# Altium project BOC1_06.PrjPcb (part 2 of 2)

## Sheet BOC_Boot.SchDoc: Board-On-Chip Bootup Circuits
size B; Organization: Altium Limited; Address1: L3, 12a Rodborough Rd; Address2: Frenchs Forest; Address3: NSW; Address4: Australia 2086; Revision: 1.06; SheetNumber: 2; SheetTotal: 16
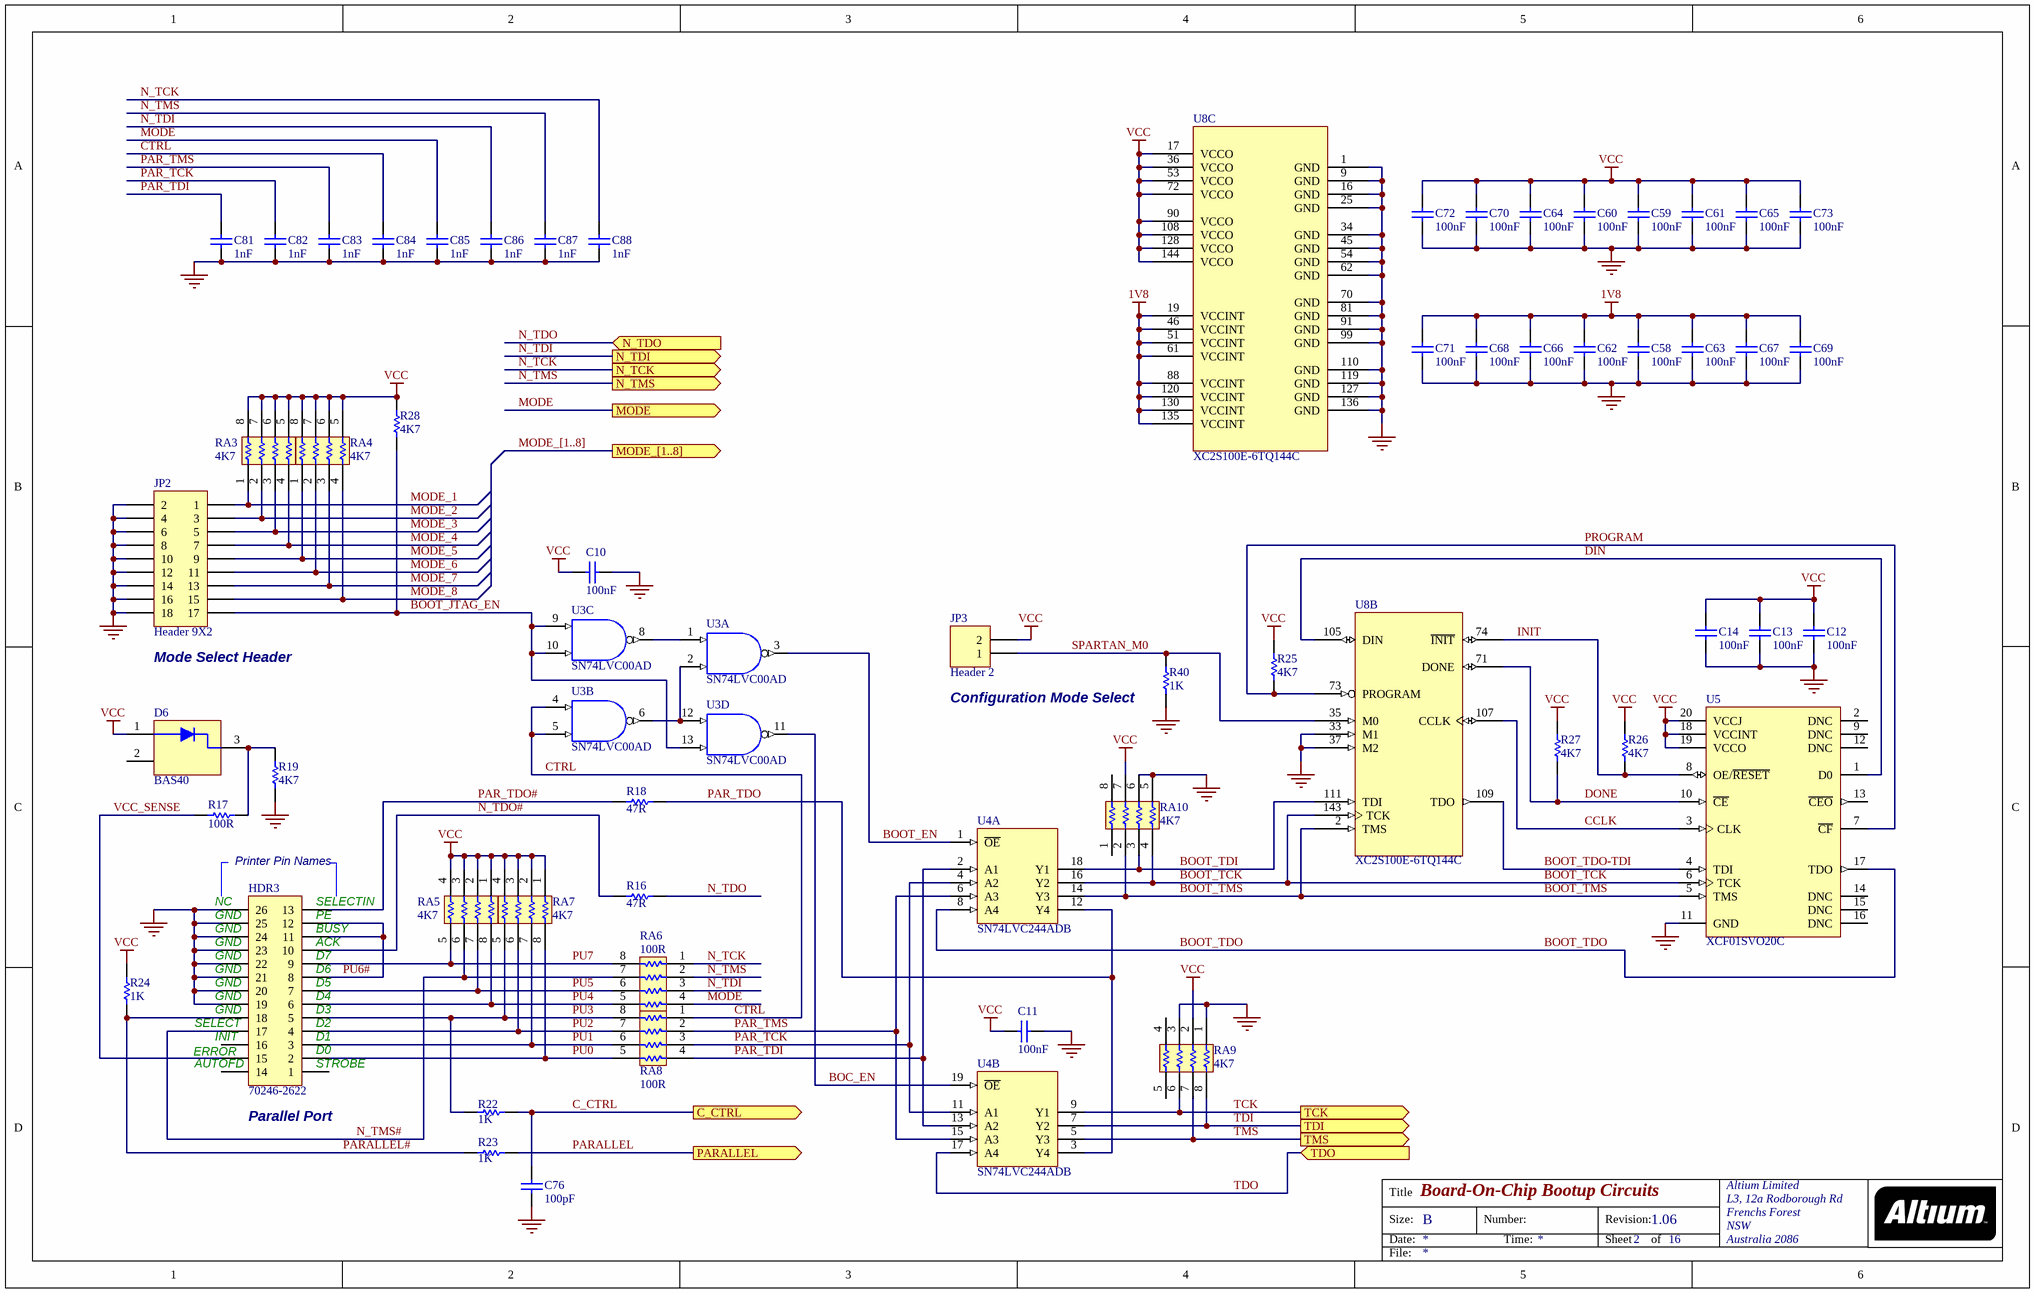
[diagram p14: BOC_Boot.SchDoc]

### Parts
C10  100nF  [CC2012-0805]
C11  100nF  [CC2012-0805]
C12  100nF  [CC2012-0805]
C13  100nF  [CC2012-0805]
C14  100nF  [CC2012-0805]
C58  100nF  [CC2012-0805]
C59  100nF  [CC2012-0805]
C60  100nF  [CC2012-0805]
C61  100nF  [CC2012-0805]
C62  100nF  [CC2012-0805]
C63  100nF  [CC2012-0805]
C64  100nF  [CC2012-0805]
C65  100nF  [CC2012-0805]
C66  100nF  [CC2012-0805]
C67  100nF  [CC2012-0805]
C68  100nF  [CC2012-0805]
C69  100nF  [CC2012-0805]
C70  100nF  [CC2012-0805]
C71  100nF  [CC2012-0805]
C72  100nF  [CC2012-0805]
C73  100nF  [CC2012-0805]
C76  100pF  [CC2012-0805]
C81  1nF  [CC2012-0805]
C82  1nF  [CC2012-0805]
C83  1nF  [CC2012-0805]
C84  1nF  [CC2012-0805]
C85  1nF  [CC2012-0805]
C86  1nF  [CC2012-0805]
C87  1nF  [CC2012-0805]
C88  1nF  [CC2012-0805]
D6  BAS40  [SO-G3]
HDR3  70246-2622  Usage: Parallel Port  [HDR2X13_CEN_LP]
JP2  Header 9X2  Usage: Mode Select Header  [HDR2X9]
JP3  Header 2  Usage: Configuration Mode Select  [HDR1X2]
R16  47R  [CC2012-0805]
R17  100R  [CC2012-0805]
R18  47R  [CC2012-0805]
R19  4K7  [CC2012-0805]
R22  1K  [CC2012-0805]
R23  1K  [CC2012-0805]
R24  1K  [CC2012-0805]
R25  4K7  [CC2012-0805]
R26  4K7  [CC2012-0805]
R27  4K7  [CC2012-0805]
R28  4K7  [CC2012-0805]
R40  1K  [CC2012-0805]
RA3  4K7  [MNR34]
RA4  4K7  [MNR34]
RA5  4K7  [MNR34]
RA6  100R  [MNR34]
RA7  4K7  [MNR34]
RA8  100R  [MNR34]
RA9  4K7  [MNR34]
RA10  4K7  [MNR34]
U3  SN74LVC00AD  [SO-G14/Y2.2]  (parts A,B,C,D of 4)
U4  SN74LVC244ADB  [SSO-G20/P.65]  (parts A,B of 2)
U5  XCF01SVO20C  [VO20]
U8  XC2S100E-6TQ144C  [TQ144]  (parts B,C of 3)

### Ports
C_CTRL (out), MODE (out), MODE_[1..8] (out), N_TCK (out), N_TDI (out), N_TDO (in), N_TMS (out), PARALLEL (out), TCK (out), TDI (out), TDO (in), TMS (out)

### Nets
1V8: C58.1 C62.1 C63.1 C66.1 C67.1 C68.1 C69.1 C71.1 U8.19(VCCINT) U8.46(VCCINT) U8.51(VCCINT) U8.61(VCCINT) U8.88(VCCINT) U8.120(VCCINT) U8.130(VCCINT) U8.135(VCCINT)
GND: C10.2 C11.2 C12.1 C13.1 C14.1 C58.2 C59.2 C60.2 C61.2 C62.2 C63.2 C64.2 C65.2 C66.2 C67.2 C68.2 C69.2 C70.2 C71.2 C72.2 C73.2 C76.2 C81.2 C82.2 C83.2 C84.2 C85.2 C86.2 C87.2 C88.2 HDR3.19 HDR3.20 HDR3.21 HDR3.22 HDR3.23 HDR3.24 HDR3.25 HDR3.26 JP2.2 JP2.4 JP2.6 JP2.8 JP2.10 JP2.12 JP2.14 JP2.16 JP2.18 R19.2 R40.1 RA9.1 RA9.3 RA10.5 RA10.6 U3.7(GND) U4.10(GND) U5.11(GND) U8.1(GND) U8.9(GND) U8.16(GND) U8.25(GND) U8.33(M1) U8.34(GND) U8.37(M2) U8.45(GND) U8.54(GND) U8.62(GND) U8.70(GND) U8.81(GND) U8.91(GND) U8.99(GND) U8.110(GND) U8.119(GND) U8.127(GND) U8.136(GND)
VCC: C10.1 C11.1 C12.2 C13.2 C14.2 C59.1 C60.1 C61.1 C64.1 C65.1 C70.1 C72.1 C73.1 D6.1 JP3.2 R24.2 R25.1 R26.1 R27.1 R28.2 RA3.5 RA3.6 RA3.7 RA3.8 RA4.5 RA4.6 RA4.7 RA4.8 RA5.1 RA5.2 RA5.3 RA5.4 RA7.1 RA7.2 RA7.3 RA7.4 RA9.2 RA10.7 U3.14(VDD) U4.20(VCC) U5.18(VCCINT) U5.19(VCCO) U5.20(VCCJ) U8.17(VCCO) U8.36(VCCO) U8.53(VCCO) U8.72(VCCO) U8.90(VCCO) U8.108(VCCO) U8.128(VCCO) U8.144(VCCO)
BOC_EN: U3.11(Y) U4.19(~{OE})
BOOT_EN: U3.3(Y) U4.1(~{OE})
BOOT_JTAG_EN: JP2.17 R28.1 U3.9(A) U3.10(B) U3.13(B)
BOOT_TCK: RA10.4 U4.16(Y2) U5.6(TCK) U8.143(TCK)
BOOT_TDI: RA10.3 U4.18(Y1) U8.111(TDI)
BOOT_TDO: U4.8(A4) U5.17(TDO)
BOOT_TDO-TDI: U5.4(TDI) U8.109(TDO)
BOOT_TMS: RA10.2 U4.14(Y3) U5.5(TMS) U8.2(TMS)
C_CTRL: C76.1 R22.2 ; port C_CTRL
CCLK: U5.3(CLK) U8.107(CCLK)
CTRL: C84.1 RA8.1 U3.4(A) U3.5(B)
DIN: U5.1(D0) U8.105(DIN)
DONE: R27.2 U5.10(~{CE}) U8.71(DONE)
INIT: R26.2 U5.8(OE/~{RESET}) U8.74(~{INIT})
MODE: C85.1 RA6.4 ; port MODE
MODE_1: JP2.1 RA3.1
MODE_2: JP2.3 RA3.2
MODE_3: JP2.5 RA3.3
MODE_4: JP2.7 RA3.4
MODE_5: JP2.9 RA4.1
MODE_6: JP2.11 RA4.2
MODE_7: JP2.13 RA4.3
MODE_8: JP2.15 RA4.4
N_TCK: C88.1 RA6.1 ; port N_TCK
N_TDI: C86.1 RA6.3 ; port N_TDI
N_TDO: R16.2 ; port N_TDO
N_TDO#: HDR3.10 R16.1
N_TMS: C87.1 RA6.2 ; port N_TMS
N_TMS#: HDR3.17 RA5.6 RA6.7
PAR_TCK: C82.1 RA8.3 U4.4(A2) U4.11(A1)
PAR_TDI: C81.1 RA8.4 U4.2(A1) U4.13(A2)
PAR_TDO: R18.2 U4.3(Y4) U4.12(Y4)
PAR_TDO#: HDR3.13 R18.1
PAR_TMS: C83.1 RA8.2 U4.6(A3) U4.15(A3)
PARALLEL: R23.2 ; port PARALLEL
PARALLEL#: HDR3.18 R23.1 R24.1
PROGRAM: R25.2 U5.7(~{CF}) U8.73(PROGRAM)
PU0: HDR3.2 RA7.8 RA8.5
PU1: HDR3.3 RA7.7 RA8.6
PU2: HDR3.4 RA7.6 RA8.7
PU3: HDR3.5 R22.1 RA7.5 RA8.8
PU4: HDR3.6 RA5.8 RA6.5
PU5: HDR3.7 RA5.7 RA6.6
PU6#: HDR3.8 HDR3.11 HDR3.12
PU7: HDR3.9 RA5.5 RA6.8
SPARTAN_M0: JP3.1 R40.2 U8.35(M0)
TCK: RA9.6 U4.9(Y1) ; port TCK
TDI: RA9.8 U4.7(Y2) ; port TDI
TDO: U4.17(A4) ; port TDO
TMS: RA9.7 U4.5(Y3) ; port TMS
VCC_SENSE: HDR3.15 R17.1
NetD6_3: D6.3 R17.2 R19.1
NetU3_1: U3.1(A) U3.8(Y)
NetU3_2: U3.2(B) U3.6(Y) U3.12(A)

Not connected (* = marked no-connect by the designer): D6 2; HDR3 1 14 16; RA9 4 5; RA10 1 8; U5 2(DNC) 9(DNC) 12(DNC) 13(~{CEO}) 14(DNC) 15(DNC) 16(DNC)

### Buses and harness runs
bus MODE_[1..8] = port MODE_[1..8]

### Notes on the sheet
- (near HDR3) NC
- Printer Pin Names
- (near HDR3) SELECTIN
- (near HDR3) GND
- (near HDR3) PE
- (near HDR3) BUSY
- (near HDR3) ACK
- (near HDR3) D6
- (near HDR3) D7
- (near HDR3) SELECT
- (near HDR3) INIT
- (near HDR3) D1
- (near HDR3) D2
- (near HDR3) D3
- (near HDR3) D4
- (near HDR3) D5
- (near HDR3) ERROR
- (near HDR3) AUTOFD
- (near HDR3) STROBE
- (near HDR3) D0

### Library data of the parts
C10-C14 C58-C73 C76 C81-C88 = CAP: Capacitor; Fitted: True
D6 = BAS40: Shottky Diode; Fitted: True
HDR3 = Header 13X2A: Header, 13-Pin, Dual row; Manufacturer: Generic Components; Class I: Connector; Fitted: True
JP2 = Header 9X2: Header, 9-Pin, Dual row; Manufacturer: Generic Components; Class I: Connector; Fitted: True
JP3 = Header 2: Header, 2-Pin; Manufacturer: Generic Components; Class I: Connector; Fitted: True
R16-R19 R22-R28 R40 = RES: Resistor; Fitted: True
RA3-RA10 = MNR34: 3216x4 Resistor Array; Fitted: True
U3 = MC74HC00AD: Quad 2-Input NAND Gate; Manufacturer: Motorola; Package Information: Latest Revision: 1991; Class I: Logic; Fitted: True
U4 = 74LVC244A: Octal Buffer/Driver with 3-State Outputs; Manufacturer: Philips; Package Information: Latest Revision: 1998; Class I: Logic; Class II: Buffer/Line Driver; Fitted: True
U5 = XCF01SVO20C: XCF00S Series, Platform Flash In-System Programmable Configuration 3.3V PROM, 1-Megabit, Commercial Grade; Manufacturer: Xilinx; Package Information: Latest Revision: ver1.0, May-2003; Class I: Memory; Code - JEDEC: MO-153-AC; Fitted: True
U8 = XC2S100E-6TQ144C: Spartan-IIE 1.8V FPGA, 144-Pin TQFP, Standard Performance, Commercial Grade; Manufacturer: Xilinx; Package Information: Latest Revision: ver1.1, Oct-2002; Class I: Field Programmable Gate Array; Code - JEDEC: MS-026-BFB; Code - IPC: SQFP20X20-144; Fitted: True

## Sheet BOC_Audio.SchDoc: Board-On-Chip Audio Interface
size A; Organization: Altium Limited; Address1: L3, 12a Rodborough Rd; Address2: Frenchs Forest; Address3: NSW; Address4: Australia 2086; Revision: 1.06; SheetNumber: 3; SheetTotal: 16
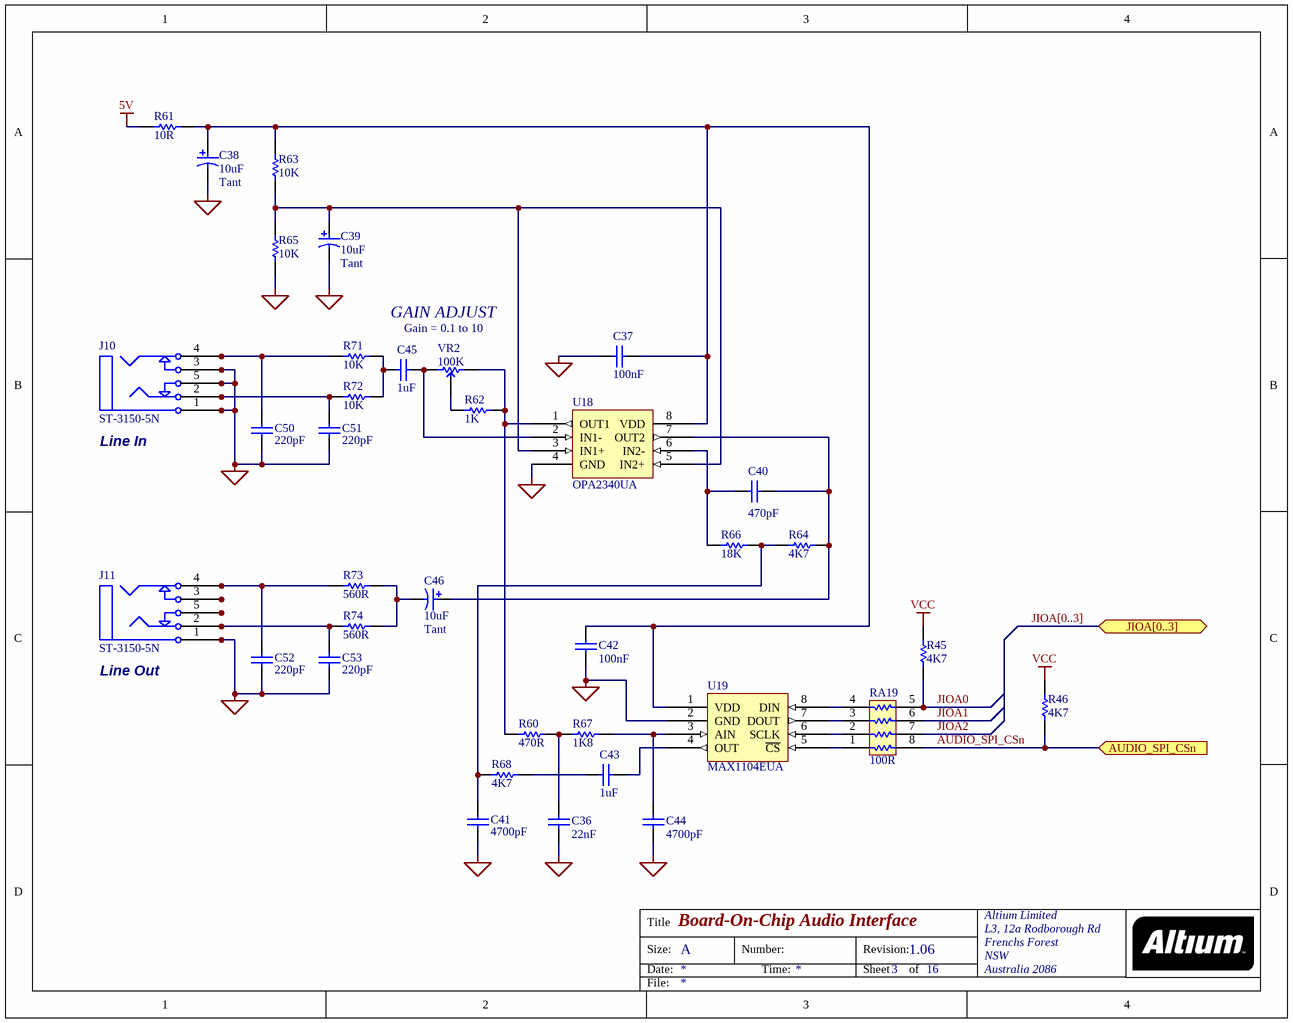
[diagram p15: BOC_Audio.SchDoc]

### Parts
C36  22nF  [CC2012-0805]
C37  100nF  [CC2012-0805]
C38  10uF  Capacitor Type: Tant  [MCCT-B]
C39  10uF  Capacitor Type: Tant  [MCCT-B]
C40  470pF  [CC2012-0805]
C41  4700pF  [CC2012-0805]
C42  100nF  [CC2012-0805]
C43  1uF  [C3216-1206]
C44  4700pF  [CC2012-0805]
C45  1uF  [C3216-1206]
C46  10uF  Capacitor Type: Tant  [MCCT-B]
C50  220pF  [CC2012-0805]
C51  220pF  [CC2012-0805]
C52  220pF  [CC2012-0805]
C53  220pF  [CC2012-0805]
J10  ST-3150-5N  [ST-3150-5N]
J11  ST-3150-5N  [ST-3150-5N]
R45  4K7  [CC2012-0805]
R46  4K7  [CC2012-0805]
R60  470R  [CC2012-0805]
R61  10R  [CC2012-0805]
R62  1K  [CC2012-0805]
R63  10K  [CC2012-0805]
R64  4K7  [CC2012-0805]
R65  10K  [CC2012-0805]
R66  18K  [CC2012-0805]
R67  1K8  [CC2012-0805]
R68  4K7  [CC2012-0805]
R71  10K  [CC2012-0805]
R72  10K  [CC2012-0805]
R73  560R  [CC2012-0805]
R74  560R  [CC2012-0805]
RA19  100R  [MNR34]
U18  OPA2340UA  [SO-G8]
U19  MAX1104EUA  [TSSO3X5-G8/X.35]
VR2  100K  [POT4MM-2]

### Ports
AUDIO_SPI_CSn (in), JIOA[0..3] (bidir)

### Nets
5V: R61.1
AGND: C36.2 C37.1 C38.2 C39.2 C41.2 C42.2 C44.2 C50.2 C51.2 C52.2 C53.2 J10.1 J10.1A J10.1B J10.3 J10.3A J10.3B J10.5 J10.5A J10.5B J11.1 J11.1A J11.1B R65.1 U18.4(GND) U19.2(GND)
VCC: R45.2 R46.2
AUDIO_SPI_CSn: R46.1 RA19.8 ; port AUDIO_SPI_CSn
JIOA0: R45.1 RA19.5
JIOA1: RA19.6
JIOA2: RA19.7
NetC36_1: C36.1 R60.2 R67.1
NetC37_2: C37.2 C38.1 C42.1 R61.2 R63.2 U18.8(VDD) U19.1(VDD)
NetC39_1: C39.1 R63.1 R65.2 U18.3(IN1+) U18.5(IN2+)
NetC40_1: C40.1 R66.2 U18.6(IN2-)
NetC40_2: C40.2 C46.1 R64.1 U18.7(OUT2)
NetC41_1: C41.1 R64.2 R66.1 R68.1
NetC43_1: C43.1 R68.2
NetC43_2: C43.2 U19.4(OUT)
NetC44_1: C44.1 R67.2 U19.3(AIN)
NetC45_1: C45.1 R71.2 R72.2
NetC45_2: C45.2 U18.2(IN1-) VR2.CCW(-)
NetC46_2: C46.2 R73.2 R74.2
NetC50_1: C50.1 J10.4 J10.4A J10.4B R71.1
NetC51_1: C51.1 J10.2 J10.2A J10.2B R72.1
NetC52_1: C52.1 J11.4 J11.4A J11.4B R73.1
NetC53_1: C53.1 J11.2 J11.2A J11.2B R74.1
NetJ11_3: J11.3 J11.3A J11.3B
NetJ11_5: J11.5 J11.5A J11.5B
NetR60_1: R60.1 R62.2 U18.1(OUT1) VR2.CW(+)
NetR62_1: R62.1 VR2.W
NetRA19_1: RA19.1 U19.5(~{CS})
NetRA19_2: RA19.2 U19.6(SCLK)
NetRA19_3: RA19.3 U19.7(DOUT)
NetRA19_4: RA19.4 U19.8(DIN)

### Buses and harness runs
bus JIOA[0..3] = port JIOA[0..3]

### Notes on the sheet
- GAIN ADJUST
- Gain = 0.1 to 10
- (near J10) Line In
- (near J11) Line Out

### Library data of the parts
C36 C37 C40-C45 C50-C53 = CAP: Capacitor; Fitted: True
C38 C39 C46 = CAP_POLAR: Polar Capacitor; Fitted: True
J10 J11 = ST-3150-5N: 3-Conductor Jack with 2 break contacts (normals) and 2 auxiliary make contacts; Manufacturer: Kycon; Class I: Connector; Fitted: True
R45 R46 R60-R68 R71-R74 = RES: Resistor; Fitted: True
RA19 = MNR34: 3216x4 Resistor Array; Fitted: True
U18 = OPA2340UA: Manufacturer: Burr-Brown; Fitted: True
U19 = MAX1104EUA: 8 bit CODEC with 4 wire logic interface; Manufacturer: Maxim; Fitted: True
VR2 = POT_M: Potentiometer; Fitted: True

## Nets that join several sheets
1V8: BOC_PWR (C21.1 C23.1 R42.1 U9.2), BOC_Boot (16 pins)
5V: BOC_IO (JP5.2 JP6.2), BOC_PWR (9 pins), BOC_ADC_DAC (HDR8.2), BOC_CAN (C4.1 J2.4 U2.3), BOC_LCD (LCD1.15 Q2.2 R30.1 R38.1), BOC_Spartan (R5.1), BOC_DAUGHTER (J8.97 J8.99 J9.97 J9.99), BOC_Audio (R61.1)
AGND: BOC_ADC_DAC (12 pins), BOC_Audio (26 pins)
GND: BOC_SRAM (6 pins), BOC_IO (HDR9.20 HDR10.20), BOC_KB (SW17.3 SW17.4), BOC_PWR (42 pins), BOC_RS232 (7 pins), BOC_ADC_DAC (HDR8.14 R80.1), BOC_CAN (7 pins), BOC_LED_DIPSWITCH (16 pins), BOC_CLK_ADJ (8 pins), BOC_LCD (16 pins), BOC_VGA_KB_MOUSE (17 pins), BOC_Spartan (36 pins), BOC_DAUGHTER (22 pins), BOC_Boot (74 pins)
VCC: BOC_SRAM (7 pins), BOC_IO (JP5.3 JP6.3), BOC_KB (5 pins), BOC_PWR (C16.1 C25.1 R47.1 U10.2), BOC_RS232 (C1.1 C2.1 C3.1 U1.16), BOC_ADC_DAC (R75.2 R77.1 R79.1), BOC_LED_DIPSWITCH (8 pins), BOC_CLK_ADJ (7 pins), BOC_LCD (5 pins), BOC_VGA_KB_MOUSE (12 pins), BOC_Spartan (32 pins), BOC_DAUGHTER (J8.94 J8.96 J9.94 J9.96), BOC_Boot (51 pins), BOC_Audio (R45.2 R46.2)
VCCINT: BOC_PWR (C24.1 C35.1 R56.1 U11.2), BOC_DAUGHTER (J8.93 J8.95 J9.93 J9.95)
AUDIO_SPI_CSn: BOC_DAUGHTER (J8.11), BOC_Audio (R46.1 RA19.8)
BLUE0: BOC_VGA_KB_MOUSE (R14.1), BOC_DAUGHTER (J8.14)
BLUE1: BOC_VGA_KB_MOUSE (R15.1), BOC_DAUGHTER (J8.16)
BOC_CTS: BOC_RS232 (R9.1), BOC_DAUGHTER (J8.13)
BOC_RTS: BOC_RS232 (U1.10), BOC_DAUGHTER (J8.17)
BOC_RX: BOC_RS232 (R1.1), BOC_DAUGHTER (J8.19)
BOC_TX: BOC_RS232 (U1.11), BOC_DAUGHTER (J8.15)
BUZZER: BOC_LCD (R37.1), BOC_DAUGHTER (J9.24)
C_CTRL: BOC_Spartan (U8.80), BOC_Boot (C76.1 R22.2)
C_SPI_CLOCK_CLK: BOC_CLK_ADJ (U12.8), BOC_Spartan (U8.141)
C_SPI_CLOCK_SEL: BOC_CLK_ADJ (R50.1 U12.9), BOC_Spartan (U8.142)
C_SPI_DIN: BOC_CLK_ADJ (U12.12), BOC_Spartan (U6.5 U7.5 U8.140)
CAN_RXD: BOC_CAN (R4.1), BOC_DAUGHTER (J8.4)
CAN_TXD: BOC_CAN (U2.1), BOC_DAUGHTER (J8.2)
FPGA_AUX0: BOC_Spartan (U8.41), BOC_DAUGHTER (J8.86)
FPGA_AUX1: BOC_Spartan (U8.42), BOC_DAUGHTER (J8.88)
FPGA_AUX2: BOC_Spartan (U8.43), BOC_DAUGHTER (J8.90)
FPGA_AUX3: BOC_Spartan (U8.44), BOC_DAUGHTER (J8.92)
FPGA_CCLK: BOC_Spartan (U8.24), BOC_DAUGHTER (J8.66)
FPGA_CLK: BOC_CLK_ADJ (R51.2 R53.2), BOC_Spartan (U8.126), BOC_DAUGHTER (J9.2)
FPGA_CLK_1: BOC_Spartan (U8.3), BOC_DAUGHTER (J8.30)
FPGA_CLK_2: BOC_Spartan (U8.4), BOC_DAUGHTER (J8.32)
FPGA_DIN: BOC_Spartan (U8.23), BOC_DAUGHTER (J8.64)
FPGA_DONE: BOC_Spartan (U8.29), BOC_DAUGHTER (J8.74)
FPGA_ID0: BOC_Spartan (U8.10), BOC_DAUGHTER (J8.42)
FPGA_ID1: BOC_Spartan (U8.8), BOC_DAUGHTER (J8.40)
FPGA_ID2: BOC_Spartan (U8.7), BOC_DAUGHTER (J8.38)
FPGA_ID3: BOC_Spartan (U8.6), BOC_DAUGHTER (J8.36)
FPGA_INIT: BOC_Spartan (U8.26), BOC_DAUGHTER (J8.68)
FPGA_INSTALLED: BOC_Spartan (R44.2 U8.5), BOC_DAUGHTER (J8.34)
FPGA_M0: BOC_Spartan (U8.21), BOC_DAUGHTER (J8.60)
FPGA_M1: BOC_Spartan (U8.20), BOC_DAUGHTER (J8.58)
FPGA_M2: BOC_Spartan (U8.18), BOC_DAUGHTER (J8.56)
FPGA_PROGRAM: BOC_Spartan (U8.22), BOC_DAUGHTER (J8.62)
FPGA_TCK: BOC_Spartan (U8.28), BOC_DAUGHTER (J8.72)
FPGA_TDI: BOC_Spartan (U8.31), BOC_DAUGHTER (J8.78)
FPGA_TDO: BOC_Spartan (RA16.1), BOC_DAUGHTER (J8.54)
FPGA_TMS: BOC_Spartan (U8.27), BOC_DAUGHTER (J8.70)
GREEN0: BOC_VGA_KB_MOUSE (R12.1), BOC_DAUGHTER (J8.10)
GREEN1: BOC_VGA_KB_MOUSE (R13.1), BOC_DAUGHTER (J8.12)
HDRIVE: BOC_VGA_KB_MOUSE (D4.3 J3.13), BOC_DAUGHTER (J8.18)
IO0: BOC_IO (HDR9.2), BOC_DAUGHTER (J9.7)
IO1: BOC_IO (HDR9.3), BOC_DAUGHTER (J9.9)
IO2: BOC_IO (HDR9.4), BOC_DAUGHTER (J9.11)
IO3: BOC_IO (HDR9.5), BOC_DAUGHTER (J9.13)
IO4: BOC_IO (HDR9.6), BOC_DAUGHTER (J9.15)
IO5: BOC_IO (HDR9.7), BOC_DAUGHTER (J9.17)
IO6: BOC_IO (HDR9.8), BOC_DAUGHTER (J9.19)
IO7: BOC_IO (HDR9.9), BOC_DAUGHTER (J9.21)
IO8: BOC_IO (HDR9.10), BOC_DAUGHTER (J9.23)
IO9: BOC_IO (HDR9.11), BOC_DAUGHTER (J9.25)
IO10: BOC_IO (HDR9.12), BOC_DAUGHTER (J9.27)
IO11: BOC_IO (HDR9.13), BOC_DAUGHTER (J9.29)
IO12: BOC_IO (HDR9.14), BOC_DAUGHTER (J9.31)
IO13: BOC_IO (HDR9.15), BOC_DAUGHTER (J9.33)
IO14: BOC_IO (HDR9.16), BOC_DAUGHTER (J9.35)
IO15: BOC_IO (HDR9.17), BOC_DAUGHTER (J9.37)
IO16: BOC_IO (HDR9.18), BOC_DAUGHTER (J9.39)
IO17: BOC_IO (HDR9.19), BOC_DAUGHTER (J9.41)
IO18: BOC_IO (HDR10.2), BOC_DAUGHTER (J9.43)
IO19: BOC_IO (HDR10.3), BOC_DAUGHTER (J9.45)
IO20: BOC_IO (HDR10.4), BOC_DAUGHTER (J9.47)
IO21: BOC_IO (HDR10.5), BOC_DAUGHTER (J9.49)
IO22: BOC_IO (HDR10.6), BOC_DAUGHTER (J9.51)
IO23: BOC_IO (HDR10.7), BOC_DAUGHTER (J9.53)
IO24: BOC_IO (HDR10.8), BOC_DAUGHTER (J9.55)
IO25: BOC_IO (HDR10.9), BOC_DAUGHTER (J9.57)
IO26: BOC_IO (HDR10.10), BOC_DAUGHTER (J9.59)
IO27: BOC_IO (HDR10.11), BOC_DAUGHTER (J9.61)
IO28: BOC_IO (HDR10.12), BOC_DAUGHTER (J9.63)
IO29: BOC_IO (HDR10.13), BOC_DAUGHTER (J9.65)
IO30: BOC_IO (HDR10.14), BOC_DAUGHTER (J9.67)
IO31: BOC_IO (HDR10.15), BOC_DAUGHTER (J9.69)
IO32: BOC_IO (HDR10.16), BOC_DAUGHTER (J9.71)
IO33: BOC_IO (HDR10.17), BOC_DAUGHTER (J9.73)
IO34: BOC_IO (HDR10.18), BOC_DAUGHTER (J9.75)
IO35: BOC_IO (HDR10.19), BOC_DAUGHTER (J9.77)
JIOA0: BOC_Spartan (RA20.4), BOC_DAUGHTER (J8.3), BOC_Audio (R45.1 RA19.5)
JIOA1: BOC_Spartan (RA20.3), BOC_DAUGHTER (J8.5), BOC_Audio (RA19.6)
JIOA2: BOC_Spartan (RA20.2), BOC_DAUGHTER (J8.7), BOC_Audio (RA19.7)
JIOA3: BOC_Spartan (RA20.1), BOC_DAUGHTER (J8.9)
JIOB0: BOC_Spartan (RA17.1), BOC_DAUGHTER (J8.83)
JIOB1: BOC_Spartan (RA17.2), BOC_DAUGHTER (J8.85)
JIOB2: BOC_Spartan (RA17.3), BOC_DAUGHTER (J8.87)
JIOB3: BOC_Spartan (RA17.4), BOC_DAUGHTER (J8.89)
KBCLOCK: BOC_VGA_KB_MOUSE (J4.5 RA2.1), BOC_DAUGHTER (J8.22)
KBDATA: BOC_VGA_KB_MOUSE (J4.1 RA2.2), BOC_DAUGHTER (J8.24)
LCD_BCKL: BOC_LCD (R35.1), BOC_DAUGHTER (J9.22)
LCD_E: BOC_LCD (LCD1.6 R29.1 U16.2), BOC_DAUGHTER (J9.26)
LED0: BOC_LED_DIPSWITCH (LED0.1), BOC_DAUGHTER (J9.60)
LED1: BOC_LED_DIPSWITCH (LED1.1), BOC_DAUGHTER (J9.62)
LED2: BOC_LED_DIPSWITCH (LED2.1), BOC_DAUGHTER (J9.64)
LED3: BOC_LED_DIPSWITCH (LED3.1), BOC_DAUGHTER (J9.66)
LED4: BOC_LED_DIPSWITCH (LED4.1), BOC_DAUGHTER (J9.68)
LED5: BOC_LED_DIPSWITCH (LED5.1), BOC_DAUGHTER (J9.70)
LED6: BOC_LED_DIPSWITCH (LED6.1), BOC_DAUGHTER (J9.72)
LED7: BOC_LED_DIPSWITCH (LED7.1), BOC_DAUGHTER (J9.74)
MODE: BOC_Spartan (U8.82), BOC_Boot (C85.1 RA6.4)
MODE_1: BOC_Spartan (U8.97), BOC_Boot (JP2.1 RA3.1)
MODE_2: BOC_Spartan (U8.96), BOC_Boot (JP2.3 RA3.2)
MODE_3: BOC_Spartan (U8.95), BOC_Boot (JP2.5 RA3.3)
MODE_4: BOC_Spartan (U8.94), BOC_Boot (JP2.7 RA3.4)
MODE_5: BOC_Spartan (U8.93), BOC_Boot (JP2.9 RA4.1)
MODE_6: BOC_Spartan (U8.92), BOC_Boot (JP2.11 RA4.2)
MODE_7: BOC_Spartan (U8.89), BOC_Boot (JP2.13 RA4.3)
MODE_8: BOC_Spartan (U8.87), BOC_Boot (JP2.15 RA4.4)
MOUSECLOCK: BOC_VGA_KB_MOUSE (J5.5 RA2.3), BOC_DAUGHTER (J8.26)
MOUSEDATA: BOC_VGA_KB_MOUSE (J5.1 RA2.4), BOC_DAUGHTER (J8.28)
N_TCK: BOC_Spartan (U8.85), BOC_Boot (C88.1 RA6.1)
N_TDI: BOC_Spartan (U8.83), BOC_Boot (C86.1 RA6.3)
N_TDO: BOC_Spartan (U8.86), BOC_Boot (R16.2)
N_TMS: BOC_Spartan (U8.84), BOC_Boot (C87.1 RA6.2)
NEXUS_TCK: BOC_Spartan (RA16.3), BOC_DAUGHTER (J8.82)
NEXUS_TDI: BOC_Spartan (RA16.4), BOC_DAUGHTER (J8.84)
NEXUS_TDO: BOC_Spartan (U8.30), BOC_DAUGHTER (J8.76)
NEXUS_TMS: BOC_Spartan (RA16.2), BOC_DAUGHTER (J8.80)
PARALLEL: BOC_Spartan (U8.79), BOC_Boot (R23.2)
RAM0_DATA0: BOC_SRAM (U15.11), BOC_LCD (U17.11), BOC_DAUGHTER (J9.42)
RAM0_DATA1: BOC_SRAM (U15.10), BOC_LCD (U17.12), BOC_DAUGHTER (J9.40)
RAM0_DATA2: BOC_SRAM (U15.22), BOC_LCD (U17.13), BOC_DAUGHTER (J9.38)
RAM0_DATA3: BOC_SRAM (U15.23), BOC_LCD (U17.14), BOC_DAUGHTER (J9.36)
RAM0_DATA4: BOC_SRAM (U15.7), BOC_LCD (U17.15), BOC_DAUGHTER (J9.34)
RAM0_DATA5: BOC_SRAM (U15.26), BOC_LCD (U17.16), BOC_DAUGHTER (J9.32)
RAM0_DATA6: BOC_SRAM (U15.6), BOC_LCD (U17.17), BOC_DAUGHTER (J9.30)
RAM0_DATA7: BOC_SRAM (U15.27), BOC_LCD (U17.18), BOC_DAUGHTER (J9.28)
RAM0_OE: BOC_SRAM (U15.28), BOC_DAUGHTER (J8.41)
RAM0_WE: BOC_SRAM (U15.12), BOC_DAUGHTER (J8.79)
RAM1_DATA0: BOC_SRAM (U14.6), BOC_DAUGHTER (J8.45)
RAM1_DATA1: BOC_SRAM (U14.7), BOC_DAUGHTER (J8.49)
RAM1_DATA2: BOC_SRAM (U14.10), BOC_DAUGHTER (J8.53)
RAM1_DATA3: BOC_SRAM (U14.11), BOC_DAUGHTER (J8.57)
RAM1_DATA4: BOC_SRAM (U14.22), BOC_DAUGHTER (J8.55)
RAM1_DATA5: BOC_SRAM (U14.23), BOC_DAUGHTER (J8.51)
RAM1_DATA6: BOC_SRAM (U14.26), BOC_DAUGHTER (J8.47)
RAM1_DATA7: BOC_SRAM (U14.27), BOC_DAUGHTER (J8.43)
RAM1_OE: BOC_SRAM (U14.28), BOC_DAUGHTER (J8.39)
RAM1_WE: BOC_SRAM (U14.12), BOC_DAUGHTER (J8.61)
RAM_ADDR0: BOC_SRAM (U14.1 U15.1), BOC_LCD (LCD1.4), BOC_DAUGHTER (J8.21)
RAM_ADDR1: BOC_SRAM (U14.2 U15.2), BOC_LCD (LCD1.5 U17.1), BOC_DAUGHTER (J8.25)
RAM_ADDR2: BOC_SRAM (U14.3 U15.3), BOC_DAUGHTER (J8.29)
RAM_ADDR3: BOC_SRAM (U14.4 U15.4), BOC_DAUGHTER (J8.33)
RAM_ADDR4: BOC_SRAM (U14.13 U15.13), BOC_DAUGHTER (J8.65)
RAM_ADDR5: BOC_SRAM (U14.14 U15.14), BOC_DAUGHTER (J8.69)
RAM_ADDR6: BOC_SRAM (U14.15 U15.15), BOC_DAUGHTER (J8.73)
RAM_ADDR7: BOC_SRAM (U14.16 U15.16), BOC_DAUGHTER (J8.77)
RAM_ADDR8: BOC_SRAM (U14.17 U15.17), BOC_DAUGHTER (J8.75)
RAM_ADDR9: BOC_SRAM (U14.18 U15.18), BOC_DAUGHTER (J8.71)
RAM_ADDR10: BOC_SRAM (U14.19 U15.19), BOC_DAUGHTER (J8.67)
RAM_ADDR11: BOC_SRAM (U14.20 U15.20), BOC_DAUGHTER (J8.63)
RAM_ADDR12: BOC_SRAM (U14.21 U15.21), BOC_DAUGHTER (J8.59)
RAM_ADDR13: BOC_SRAM (U14.29 U15.29), BOC_DAUGHTER (J8.35)
RAM_ADDR14: BOC_SRAM (U14.30 U15.30), BOC_DAUGHTER (J8.31)
RAM_ADDR15: BOC_SRAM (U14.31 U15.31), BOC_DAUGHTER (J8.27)
RAM_ADDR16: BOC_SRAM (U14.32 U15.32), BOC_DAUGHTER (J8.23)
RAM_CS: BOC_SRAM (R59.2 U14.5 U15.5), BOC_DAUGHTER (J8.37)
RED0: BOC_VGA_KB_MOUSE (R10.1), BOC_DAUGHTER (J8.6)
RED1: BOC_VGA_KB_MOUSE (R11.1), BOC_DAUGHTER (J8.8)
REF_CLK: BOC_CLK_ADJ (R52.2 R54.2), BOC_Spartan (U8.129), BOC_DAUGHTER (J9.4)
SCL: BOC_ADC_DAC (HDR8.3 R78.1 R79.2), BOC_DAUGHTER (J9.5)
SDA: BOC_ADC_DAC (HDR8.4 R76.1 R77.2), BOC_DAUGHTER (J9.3)
SPI_CLK: BOC_Spartan (U8.12), BOC_DAUGHTER (J8.46)
SPI_DIN: BOC_Spartan (U8.11), BOC_DAUGHTER (J8.44)
SPI_DOUT: BOC_Spartan (U8.14), BOC_DAUGHTER (J8.50)
SPI_MODE: BOC_Spartan (U8.15), BOC_DAUGHTER (J8.52)
SPI_SEL: BOC_Spartan (U8.13), BOC_DAUGHTER (J8.48)
SW0: BOC_LED_DIPSWITCH (RA21.1 S2.1), BOC_DAUGHTER (J9.44)
SW1: BOC_LED_DIPSWITCH (RA21.2 S2.2), BOC_DAUGHTER (J9.46)
SW2: BOC_LED_DIPSWITCH (RA21.3 S2.3), BOC_DAUGHTER (J9.48)
SW3: BOC_LED_DIPSWITCH (RA21.4 S2.4), BOC_DAUGHTER (J9.50)
SW4: BOC_LED_DIPSWITCH (RA22.1 S2.5), BOC_DAUGHTER (J9.52)
SW5: BOC_LED_DIPSWITCH (RA22.2 S2.6), BOC_DAUGHTER (J9.54)
SW6: BOC_LED_DIPSWITCH (RA22.3 S2.7), BOC_DAUGHTER (J9.56)
SW7: BOC_LED_DIPSWITCH (RA22.4 S2.8), BOC_DAUGHTER (J9.58)
SWC0: BOC_KB (9 pins), BOC_DAUGHTER (J9.18)
SWC1: BOC_KB (9 pins), BOC_DAUGHTER (J9.16)
SWC2: BOC_KB (9 pins), BOC_DAUGHTER (J9.14)
SWC3: BOC_KB (9 pins), BOC_DAUGHTER (J9.6)
SWR0: BOC_KB (8 pins), BOC_DAUGHTER (J9.20)
SWR1: BOC_KB (8 pins), BOC_DAUGHTER (J9.12)
SWR2: BOC_KB (8 pins), BOC_DAUGHTER (J9.10)
SWR3: BOC_KB (8 pins), BOC_DAUGHTER (J9.8)
TCK: BOC_Spartan (U8.78), BOC_Boot (RA9.6 U4.9)
TDI: BOC_Spartan (U8.77), BOC_Boot (RA9.8 U4.7)
TDO: BOC_Spartan (U8.75), BOC_Boot (U4.17)
TEST: BOC_KB (R55.2 SW17.1 SW17.2), BOC_DAUGHTER (J8.81)
TMS: BOC_Spartan (U8.76), BOC_Boot (RA9.7 U4.5)
VDRIVE: BOC_VGA_KB_MOUSE (D5.3 J3.14), BOC_DAUGHTER (J8.20)
VREF: BOC_PWR (R56.2 R57.1 U11.1), BOC_DAUGHTER (J8.91)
